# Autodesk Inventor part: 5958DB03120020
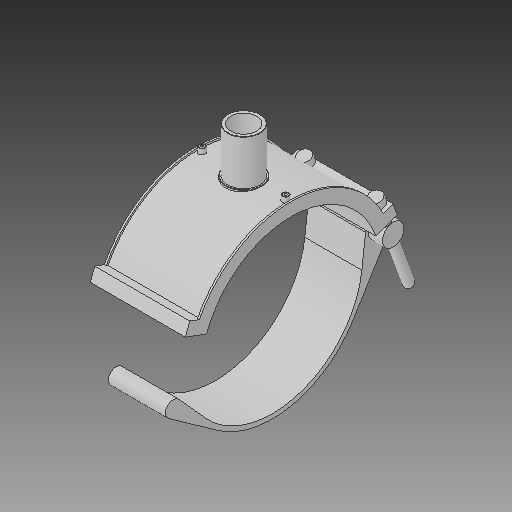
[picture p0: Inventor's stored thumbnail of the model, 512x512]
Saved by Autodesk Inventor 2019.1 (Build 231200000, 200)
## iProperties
Created: 2017-07
Part Number: 5958DB03120020
Material: Generic
Description: PLASSON BRANCH SADDLE 12''DIPS x 2''IPS
Document SubType Name: Modeling
Designer: KIM
Mass: 764.267 g
Surface Area: 1930.38 cm^2
Volume: 764.267 cm^3
Density: 1 g/cm^3
Appearance: Default
Author: KIM
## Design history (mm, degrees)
derived "5958D (2).ipt"
feature "Solid6::5958D (2).ipt"
tag "TaggingFeature1"
body "Solid1"
other parameters: "d_" = 333.8, "d1" = 60.1, "B_" = 180.594, "H_" = 104.902, "H1" = 84.074, "L" = 176.022, "t" = 6, "d244" = 333.8, "d245" = 20.828, "d248" = 180.594, "d249" = 90.297, "d252" = 166.9, "d254" = 20.828, "d256" = 541.782, "d257" = 41.725, "d258" = 270.891, "d259" = 0.5, "d260" = 176.022, "d261" = 0, "d287" = 188.56112, "d288" = 66.11, "d290" = 0, "d291" = 271.802, "d292" = 60.1, "d294" = 0, "d309" = 196.9, "d310" = 12, "d311" = 12, "d315" = 3 deg, "d316" = 4, "d318" = 4, "d320" = 14, "d321" = 0, "d331" = 0.601, "d332" = 48.08, "d334" = 0, "d337" = 0.601, "d340" = 10.56132, "d341" = 10.56132, "d342" = 20 deg, "d343" = 20 deg, "d344" = 722.376, "d345" = 333.8, "d347" = 0, "d352" = 41.656, "d353" = 23.366, "d355" = 0, "d356" = 20 deg, "d357" = 50.07, "d358" = 333.8, "d359" = 350.49, "d360" = 40.056, "d361" = 10 deg, "d362" = 9.26846, "d363" = 66.76, "d366" = 183.59, "d367" = 9.68502, "d368" = 105.6132, "d369" = 0, "d370" = 158.4198, "d371" = 0, "d372" = 132.0165, "d374" = 16.69, "d375" = 23.366, "d376" = 16.69, "d377" = 23.366, "d378" = 166.9, "d379" = 0, "d380" = 14.0196, "d381" = 0, "d383" = 198.142, "d384" = 17.6022, "d385" = 3.338, "d386" = 3.52044, "d387" = 0, "d389" = 360 deg
